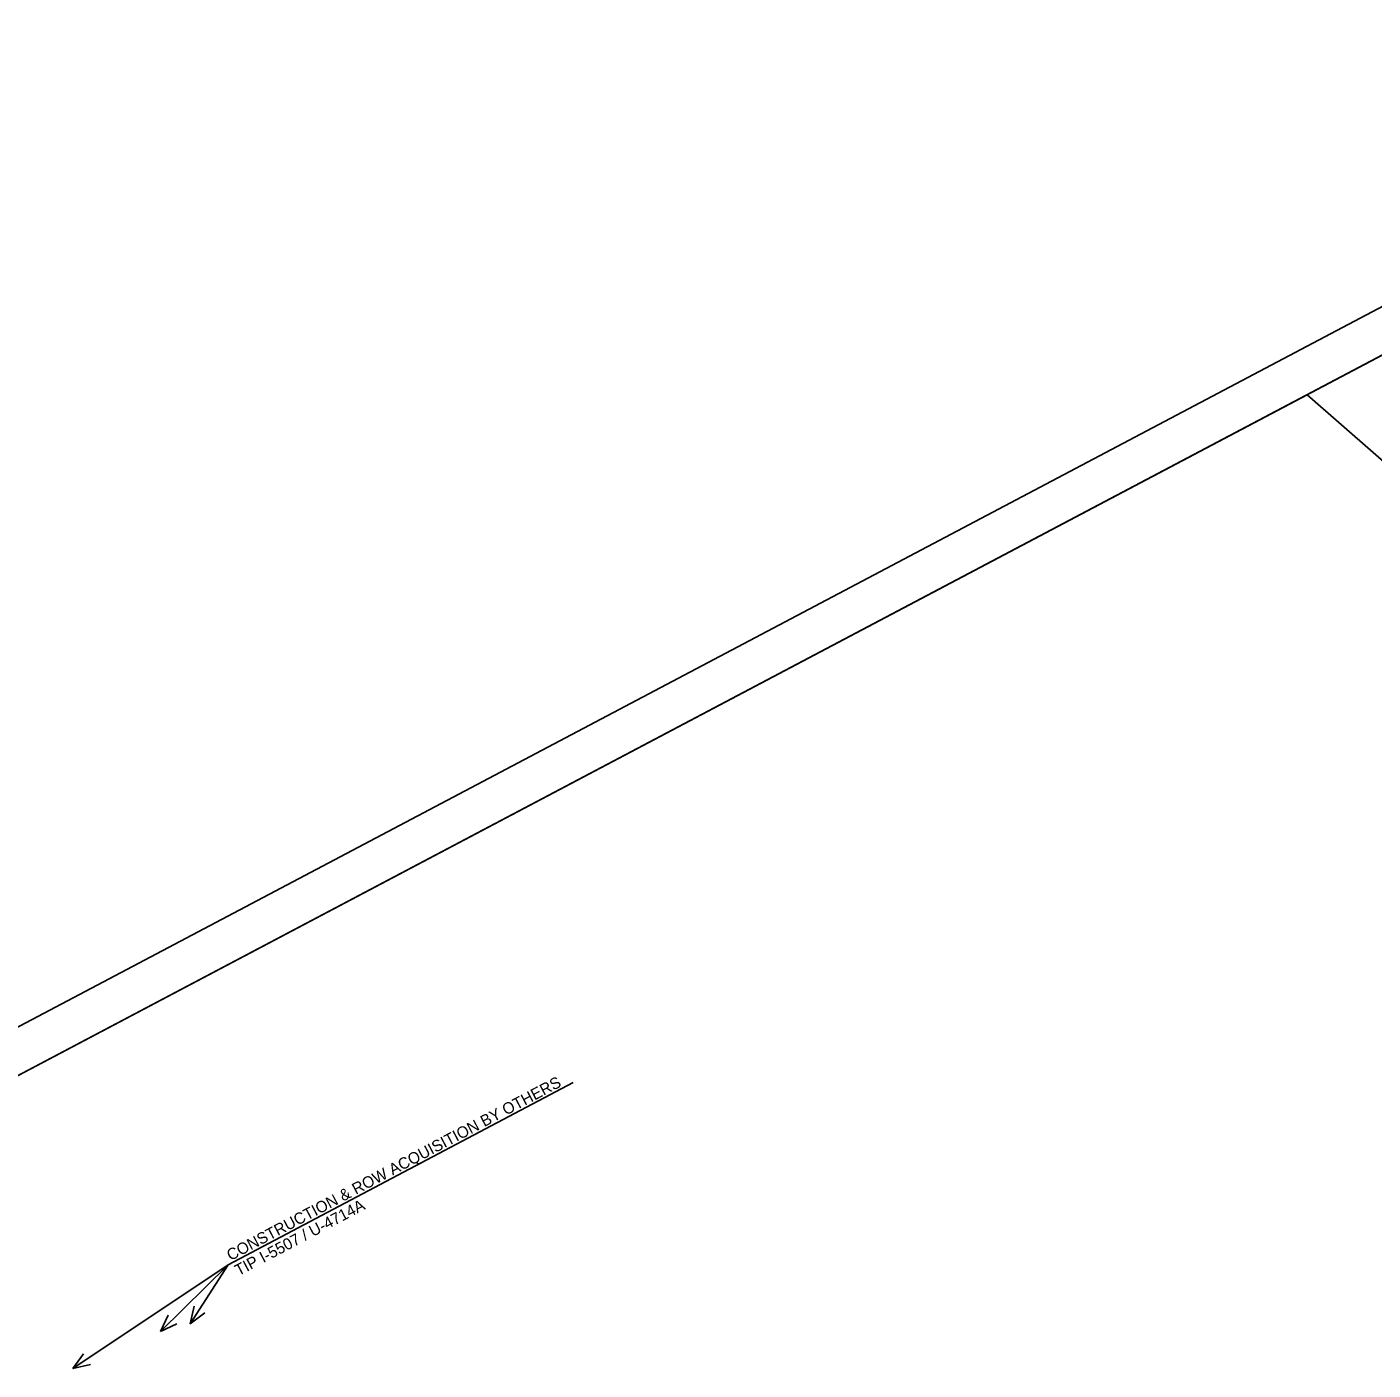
# Model space of a CAD drawing. Extents: x 1486642 to 1489051, y 497560 to 499336.
# Drawn here: x 1487550 to 1488257, y 498631 to 499336 of the extents above; entities that cross this region are included whole.
import ezdxf

# ---------------------------------------------------------------- set-up
doc = ezdxf.new("R2010")
doc.units = 0
for name, color, linetype in [('Prop Horizontal Alignment Station Label', 7, 'Continuous'), ('Sheet Clip Boundary CELL', 7, 'Continuous'), ('Sheet Plan CELL', 7, 'Continuous'), ('Sheet Plot Border Outside CELL', 7, 'Continuous')]:
    doc.layers.add(name, color=color, linetype=linetype)

msp = doc.modelspace()

# ---------------------------------------------------------------- linework, layer by layer
at = {"layer": 'Prop Horizontal Alignment Station Label'}
for p, q in [((1487655.56, 498686.3), (1487836.75, 498781.98)), ((1487655.56, 498686.3), (1487573.92, 498631.77)), ((1487655.56, 498686.3), (1487619.91, 498651.26)), ((1487655.56, 498686.3), (1487635.54, 498655.34)), ((1487624.04, 498659.89), (1487619.91, 498651.26)), ((1487637.69, 498664.66), (1487635.54, 498655.34)), ((1487643.19, 498661.11), (1487635.54, 498655.34)), ((1487628.64, 498655.22), (1487619.91, 498651.26)), ((1487579.6, 498639.48), (1487573.92, 498631.77)), ((1487583.24, 498634.03), (1487573.92, 498631.77))]:
    msp.add_line(p, q, dxfattribs=at)
at = {"layer": 'Sheet Clip Boundary CELL'}
msp.add_lwpolyline([(1487208.67, 498608.12), (1488222.07, 499143.22), (1488965.38, 498493.67), (1489025.4, 498380.01), (1487698.94, 497679.61)], close=True, dxfattribs=at)
at = {"layer": 'Sheet Plan CELL'}
for points in [[(1488535.14, 499308.53), (1487208.67, 498608.12), (1487698.94, 497679.61), (1489025.4, 498380.01)], [(1487698.94, 497679.61), (1487208.66, 498608.09), (1488358.21, 499215.12), (1488428.29, 499082.43), (1488605.19, 499175.82), (1489025.4, 498380.01)]]:
    msp.add_lwpolyline(points, close=True, dxfattribs=at)
at = {"layer": 'Sheet Plot Border Outside CELL'}
msp.add_lwpolyline([(1487562.23, 497581.96), (1489050.94, 498368.04), (1488539.66, 499336.34), (1487050.94, 498550.27)], close=True, dxfattribs=at)

# ---------------------------------------------------------------- texts
at = {"layer": 'Prop Horizontal Alignment Station Label'}
for s, p in [('CONSTRUCTION & ROW ACQUISITION BY OTHERS', (1487656.74, 498688.23)), ('TIP I-5507 / U-4714A', (1487660.94, 498680.27))]:
    msp.add_text(s, height=6, rotation=27.83509, dxfattribs=at).set_placement(p)

doc.saveas('drawing.dxf')
